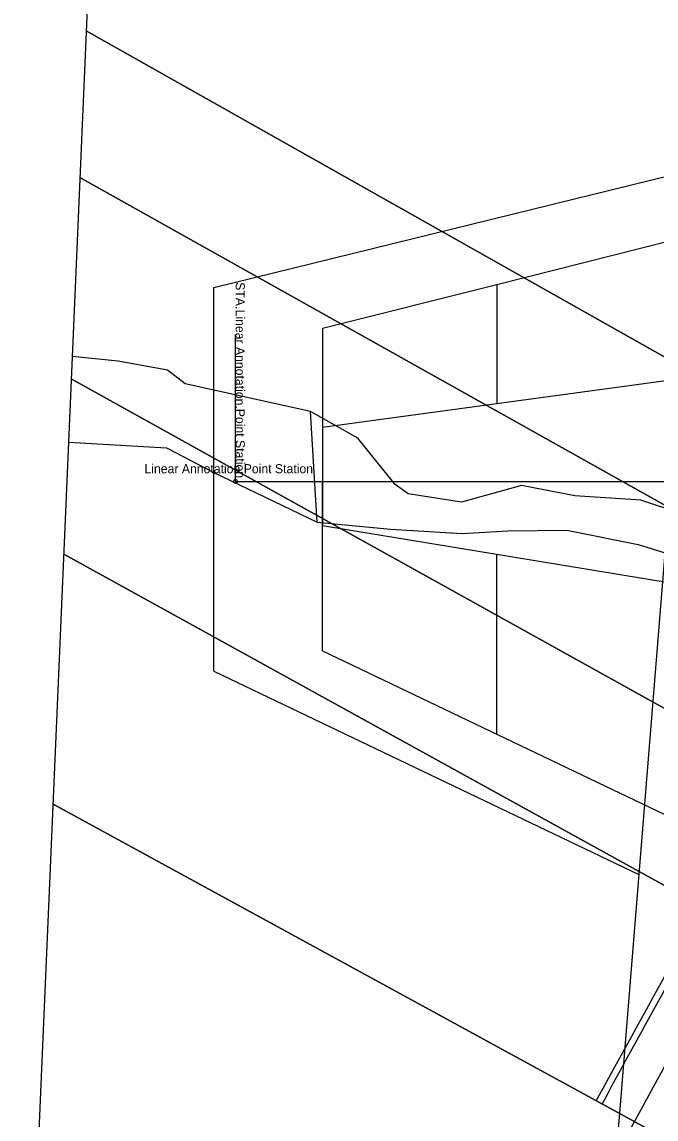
# Model space of a CAD drawing. Extents: x -1609 to 1184, y -412 to 394.
# Drawn here: x -90 to -60.9, y 281.7 to 332.1 of the extents above; entities that cross this region are included whole.
import ezdxf

# ---------------------------------------------------------------- set-up
doc = ezdxf.new("R2010")
doc.units = 0
for name, color, linetype in [('DT_P_Slope_Break_Line', 7, 'Continuous'), ('DT_X_Slope_Break_Line', 7, 'Continuous'), ('GE_P_Alignment_100_Cardinal_Points', 7, 'Continuous'), ('GE_P_Alignment_100_Stations', 7, 'Continuous'), ('GE_P_CL_10', 7, 'Continuous'), ('HY_P_Water_Edge', 7, 'Continuous'), ('HY_X_Water_Edge', 7, 'Continuous'), ('PV_P_Shoulder', 7, 'Continuous'), ('RW_P_Const_Limits', 7, 'Continuous'), ('RW_X_Esmt_SH', 7, 'Continuous'), ('SH_Data', 7, 'Continuous'), ('SH_Named_Boundary', 7, 'Continuous')]:
    doc.layers.add(name, color=color, linetype=linetype)

msp = doc.modelspace()

# ---------------------------------------------------------------- linework, layer by layer
at = {"layer": 'DT_P_Slope_Break_Line'}
for p, q in [((-68.213, 320.055), (-60.213, 322.066)), ((-76.213, 318.044), (-68.213, 320.055)), ((-68.213, 320.055), (-68.213, 314.578)), ((-76.213, 313.494), (-76.213, 308.974)), ((-68.213, 299.377), (-68.213, 307.651)), ((-76.213, 303.204), (-58.779, 294.865))]:
    msp.add_line(p, q, dxfattribs=at)
at = {"layer": 'DT_X_Slope_Break_Line'}
for p, q in [((-76.213, 318.044), (-76.213, 313.494)), ((-76.213, 303.204), (-76.213, 308.974))]:
    msp.add_line(p, q, dxfattribs=at)
at = {"layer": 'GE_P_Alignment_100_Cardinal_Points'}
msp.add_line((-80.213, 310.994), (-80.213, 317.744), dxfattribs=at)
msp.add_circle((-80.213, 310.994), 0.09, dxfattribs=at)
at = {"layer": 'GE_P_Alignment_100_Stations'}
msp.add_line((-80.213, 310.994), (-80.213, 311.294), dxfattribs=at)
at = {"layer": 'GE_P_CL_10'}
msp.add_line((-80.213, 310.994), (69.787, 310.994), dxfattribs=at)
at = {"layer": 'HY_P_Water_Edge'}
for p, q in [((-76.213, 313.494), (-60.213, 315.661)), ((-76.213, 308.974), (-60.213, 306.328))]:
    msp.add_line(p, q, dxfattribs=at)
at = {"layer": 'HY_X_Water_Edge'}
for points in [[(-39.289, 311.596), (-41.436, 311.358), (-44.991, 309.658), (-47.55, 309.164), (-50.467, 309.563), (-53.289, 309.434), (-54.718, 308.89), (-56.588, 308.066), (-57.795, 308.876), (-61.598, 310.136), (-64.624, 310.339), (-67.074, 310.8), (-69.83, 310.044), (-72.278, 310.418), (-72.882, 310.855), (-74.6, 312.98), (-76.765, 314.202), (-82.524, 315.483), (-83.34, 316.111), (-85.597, 316.524), (-87.712, 316.736)], [(-87.881, 312.805), (-83.379, 312.539), (-81.246, 311.423), (-76.467, 309.116), (-73.071, 308.792), (-69.807, 308.601), (-67.705, 308.729), (-64.994, 308.754), (-61.714, 308.101), (-57.168, 306.683), (-54.895, 306.796), (-50.085, 305.954), (-47.184, 305.816), (-45.992, 305.44), (-44.795, 305.228), (-43.58, 304.105)]]:
    msp.add_lwpolyline(points, dxfattribs=at)
at = {"layer": 'PV_P_Shoulder'}
msp.add_line((-76.467, 309.116), (-76.765, 314.202), dxfattribs=at)
at = {"layer": 'RW_P_Const_Limits'}
for p, q in [((-81.213, 319.905), (-60.213, 325.067)), ((-81.213, 310.994), (-81.213, 319.905)), ((-81.213, 302.271), (-81.213, 310.994)), ((-60.316, 309.798), (-62.578, 281.948)), ((-81.213, 302.271), (-61.686, 292.929)), ((-62.578, 281.948), (-63.864, 266.112))]:
    msp.add_line(p, q, dxfattribs=at)
at = {"layer": 'RW_X_Esmt_SH'}
msp.add_arc((1944.751, -814.821), 2286.626, 149.054448, 151.865024, dxfattribs=at)
at = {"layer": 'SH_Data'}
msp.add_line((-76.213, 306.328), (-76.213, 310.994), dxfattribs=at)
at = {"layer": 'SH_Named_Boundary'}
for p, q in [((-16.213, 291.723), (-87.069, 331.706)), ((-87.069, 331.706), (-87.069, 331.706)), ((-87.069, 331.706), (-16.213, 291.723)), ((23.64, 262.708), (-87.358, 324.966)), ((-87.358, 324.966), (-87.358, 324.966)), ((-87.358, 324.966), (23.64, 262.708)), ((23.64, 262.708), (-87.358, 324.966)), ((-87.358, 324.966), (-87.358, 324.966)), ((-87.358, 324.966), (23.64, 262.708)), ((7.316, 262.833), (-87.756, 315.715)), ((-87.756, 315.715), (-87.756, 315.715)), ((-87.756, 315.715), (7.316, 262.833)), ((-7.144, 262.944), (-88.103, 307.647)), ((-88.103, 307.647), (-88.103, 307.647)), ((-88.103, 307.647), (-7.144, 262.944)), ((-7.144, 262.944), (-88.103, 307.647)), ((-88.103, 307.647), (-88.103, 307.647)), ((-88.103, 307.647), (-7.144, 262.944)), ((-28.09, 263.104), (-88.596, 296.164)), ((-88.596, 296.164), (-88.596, 296.164)), ((-88.596, 296.164), (-28.09, 263.104)), ((-28.09, 263.104), (-88.596, 296.164)), ((-88.596, 296.164), (-88.596, 296.164)), ((-88.596, 296.164), (-28.09, 263.104))]:
    msp.add_line(p, q, dxfattribs=at)
msp.add_lwpolyline([(-24.862, 360.994), (-85.817, 360.841), (-90.022, 262.992), (-75.962, 263.471), (77.102, 262.298), (78.946, 360.994)], close=True, dxfattribs=at)
for radius, start in [(2288.626, 150.71244), (2288.326, 151.094136)]:
    msp.add_arc((1944.752, -814.821), radius, start, 151.3486, dxfattribs=at)

# ---------------------------------------------------------------- texts
at = {"layer": 'GE_P_Alignment_100_Cardinal_Points'}
for s, p in [(' STA. ', (-80.206, 320.311)), ('Linear Annotation.Point Station', (-80.206, 318.893))]:
    msp.add_text(s, height=0.42, rotation=269.9999, dxfattribs=at).set_placement(p)
at = {"layer": 'GE_P_Alignment_100_Stations'}
msp.add_text('Linear Annotation.Point Station', height=0.42, rotation=359.9999, dxfattribs=at).set_placement((-84.395, 311.369))

doc.saveas('drawing.dxf')
